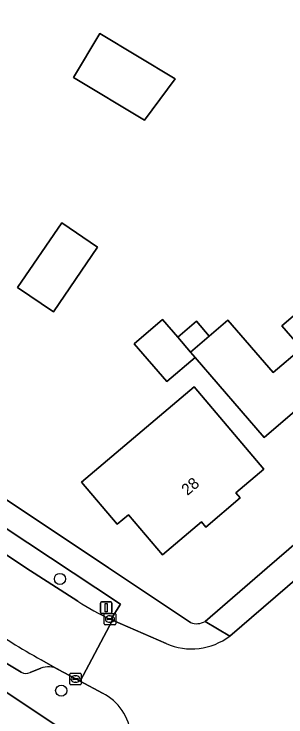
# Model space of a CAD drawing. Extents: x 161772 to 163126, y 383092 to 383917.
# Drawn here: x 162409.9 to 162433.7, y 383487 to 383548.4 of the extents above; entities that cross this region are included whole.
import ezdxf

# ---------------------------------------------------------------- set-up
doc = ezdxf.new("R2010")
doc.units = 0
for name, color, linetype in [('IMGEO_Boom', 7, 'Continuous'), ('IMGEO_Erf', 7, 'Continuous'), ('IMGEO_Groenvoorziening', 7, 'Continuous'), ('IMGEO_Kolk', 7, 'Continuous'), ('IMGEO_Lichtmast', 7, 'Continuous'), ('IMGEO_Pand', 7, 'Continuous'), ('IMGEO_Pand_nummerreeks', 7, 'Continuous'), ('IMGEO_Parkeervlak_open', 7, 'Continuous'), ('IMGEO_Rijbaan_lokaal_gesloten', 7, 'Continuous'), ('IMGEO_Rijbaan_lokaal_open', 7, 'Continuous'), ('IMGEO_Voetpad_open', 7, 'Continuous')]:
    doc.layers.add(name, color=color, linetype=linetype)

msp = doc.modelspace()

# ---------------------------------------------------------------- linework, layer by layer
at = {"layer": 'IMGEO_Boom'}
for centre in [(162413.947, 383499.021), (162414.061, 383489.255)]:
    msp.add_circle(centre, 0.489, dxfattribs=at)
at = {"layer": 'IMGEO_Erf'}
for points in [[(162462.704, 383536.779), (162483.744, 383554.98), (162500, 383574.599), (162526.947, 383607.122), (162543.804, 383623.317), (162548.918, 383628.126), (162539.791, 383641.093), (162527.133, 383641.683), (162527.105, 383641.456), (162500, 383642.583), (162442.25, 383644.984), (162375.184, 383528.714), (162418.191, 383500), (162425.357, 383495.215)], [(162426.613, 383495.312), (162432.045, 383500), (162467.807, 383530.859), (162462.704, 383536.779)], [(162434.864, 383514.039), (162431.773, 383511.379), (162425.74, 383518.391), (162423.277, 383516.272), (162420.44, 383519.57), (162422.904, 383521.69), (162424.234, 383520.144), (162425.864, 383521.546), (162426.986, 383520.242), (162428.616, 383521.645), (162432.564, 383517.058), (162435.022, 383519.173), (162433.324, 383521.146), (162436.75, 383524.093)], [(162415.606, 383482.867), (162415.154, 383485.181), (162392.934, 383500), (162369.796, 383515.431)]]:
    msp.add_lwpolyline(points, dxfattribs=at)
for points in [[(162421.34, 383539.125), (162415.121, 383542.854), (162417.421, 383546.689), (162423.997, 383542.746)], [(162413.371, 383522.37), (162410.247, 383524.505), (162414.104, 383530.149), (162417.228, 383528.014)], [(162431.752, 383508.605), (162429.312, 383506.539), (162429.685, 383506.099), (162426.677, 383503.551), (162426.294, 383504.003), (162422.898, 383501.127), (162419.935, 383504.627), (162418.955, 383503.798), (162415.83, 383507.489), (162425.654, 383515.806)]]:
    msp.add_lwpolyline(points, close=True, dxfattribs=at)
msp.add_arc((162425.891, 383496.486), 1.378, 247.22579, 301.6065, dxfattribs=at)
at = {"layer": 'IMGEO_Groenvoorziening'}
for points in [[(162418.384, 383495.476), (162419.246, 383496.818), (162417.08, 383498.245), (162405.174, 383506.099), (162404.404, 383504.955)], [(162404.404, 383504.955), (162404.125, 383504.54), (162404.195, 383504.494), (162406.79, 383502.794), (162410.958, 383500), (162415.501, 383497.08)]]:
    msp.add_lwpolyline(points, dxfattribs=at)
msp.add_arc((162428.804, 383517.598), 24.454, 237.04199, 244.77796, dxfattribs=at)
at = {"layer": 'IMGEO_Kolk'}
for p, q in [((162417.812, 383495.085), (162417.812, 383495.937)), ((162417.887, 383496.011), (162418.739, 383496.011)), ((162418.813, 383495.937), (162418.813, 383495.085)), ((162418.071, 383495.505), (162418.071, 383495.517)), ((162418.509, 383495.468), (162418.111, 383495.468)), ((162418.114, 383495.554), (162418.512, 383495.554)), ((162418.3, 383495.791), (162418.325, 383495.791)), ((162418.555, 383495.517), (162418.555, 383495.505)), ((162418.739, 383495.011), (162417.887, 383495.011)), ((162418.323, 383495.231), (162418.298, 383495.231)), ((162414.801, 383489.847), (162414.801, 383490.699)), ((162414.876, 383490.773), (162415.728, 383490.773)), ((162415.289, 383490.553), (162415.314, 383490.553)), ((162415.802, 383490.699), (162415.802, 383489.847)), ((162415.728, 383489.773), (162414.876, 383489.773)), ((162415.06, 383490.267), (162415.06, 383490.279)), ((162415.498, 383490.23), (162415.1, 383490.23)), ((162415.103, 383490.316), (162415.501, 383490.316)), ((162415.312, 383489.993), (162415.287, 383489.993)), ((162415.544, 383490.279), (162415.544, 383490.267))]:
    msp.add_line(p, q, dxfattribs=at)
for points in [[(162417.812, 383495.085), (162417.812, 383495.937)], [(162417.887, 383496.011), (162418.739, 383496.011)], [(162418.813, 383495.937), (162418.813, 383495.085)], [(162418.739, 383495.011), (162417.887, 383495.011)], [(162414.801, 383489.847), (162414.801, 383490.699)], [(162414.876, 383490.773), (162415.728, 383490.773)], [(162415.802, 383490.699), (162415.802, 383489.847)], [(162415.728, 383489.773), (162414.876, 383489.773)]]:
    msp.add_lwpolyline(points, dxfattribs=at)
for centre, radius, start, end in [((162417.889, 383495.935), 0.0765, 91.55205, 178.44795), ((162417.889, 383495.935), 0.0765, 91.55205, 178.44795), ((162418.737, 383495.935), 0.0765, 1.55205, 88.44795), ((162418.737, 383495.935), 0.0765, 1.55205, 88.44795), ((162418.111, 383495.514), 0.0403, 85.87752, 175.75265), ((162418.108, 383495.504), 0.0366, 178.93798, 274.71019), ((162418.512, 383495.511), 0.043, 264.86636, 352.45326), ((162418.516, 383495.516), 0.0386, 1.73085, 96.63898), ((162417.889, 383495.087), 0.0765, 181.55205, 268.44795), ((162417.889, 383495.087), 0.0765, 181.55205, 268.44795), ((162418.737, 383495.087), 0.0765, 271.55205, 358.44795), ((162418.737, 383495.087), 0.0765, 271.55205, 358.44795), ((162414.878, 383490.697), 0.0765, 91.55205, 178.44795), ((162414.878, 383490.697), 0.0765, 91.55205, 178.44795), ((162415.726, 383490.697), 0.0765, 1.55205, 88.44795), ((162415.726, 383490.697), 0.0765, 1.55205, 88.44795), ((162414.878, 383489.849), 0.0765, 181.55205, 268.44795), ((162414.878, 383489.849), 0.0765, 181.55205, 268.44795), ((162415.1, 383490.276), 0.0403, 85.87752, 175.75265), ((162415.097, 383490.266), 0.0366, 178.93798, 274.71019), ((162415.501, 383490.273), 0.043, 264.86636, 352.45326), ((162415.505, 383490.278), 0.0386, 1.73085, 96.63898), ((162415.726, 383489.849), 0.0765, 271.55205, 358.44795), ((162415.726, 383489.849), 0.0765, 271.55205, 358.44795)]:
    msp.add_arc(centre, radius, start, end, dxfattribs=at)
for centre, major_axis, ratio, start_param, end_param in [((162418.299, 383495.511), (-0.387, 0.002), 0.722429, 4.712389, 7.853982), ((162418.324, 383495.511), (-0.39, 0.002), 0.717154, 1.570796, 4.712389), ((162415.288, 383490.273), (-0.387, 0.002), 0.722429, 4.712389, 7.853982), ((162415.313, 383490.273), (-0.39, 0.002), 0.717154, 1.570796, 4.712389)]:
    msp.add_ellipse(centre, major_axis=major_axis, ratio=ratio, start_param=start_param, end_param=end_param, dxfattribs=at)
at = {"layer": 'IMGEO_Lichtmast'}
for p, q in [((162417.487, 383496.11), (162417.487, 383496.91)), ((162417.487, 383496.91), (162417.487, 383496.11)), ((162417.587, 383497.01), (162418.377, 383497.01)), ((162418.377, 383497.01), (162417.587, 383497.01)), ((162418.477, 383496.91), (162418.477, 383496.11)), ((162418.477, 383496.11), (162418.477, 383496.91)), ((162418.377, 383496.01), (162417.587, 383496.01)), ((162417.587, 383496.01), (162418.377, 383496.01))]:
    msp.add_line(p, q, dxfattribs=at)
msp.add_lwpolyline([(162417.907, 383496.885), (162418.057, 383496.885), (162418.057, 383496.135), (162417.907, 383496.135), (162417.907, 383496.885)], dxfattribs=at)
for centre, start, end in [((162417.587, 383496.91), 90, 180), ((162417.587, 383496.91), 90, 180), ((162418.377, 383496.91), 0, 90), ((162418.377, 383496.91), 360, 90), ((162417.587, 383496.11), 180, 270), ((162417.587, 383496.11), 180, 270), ((162418.377, 383496.11), 270, 0), ((162418.377, 383496.11), 270, 0)]:
    msp.add_arc(centre, 0.1, start, end, dxfattribs=at)
at = {"layer": 'IMGEO_Pand'}
for points in [[(162421.34, 383539.125), (162423.997, 383542.746), (162417.421, 383546.689), (162415.121, 383542.854)], [(162413.371, 383522.37), (162417.228, 383528.014), (162414.104, 383530.149), (162410.247, 383524.505)], [(162436.844, 383524.173), (162436.75, 383524.093), (162433.324, 383521.146), (162435.022, 383519.173), (162432.564, 383517.058), (162428.616, 383521.645), (162426.986, 383520.242), (162425.356, 383518.839), (162425.74, 383518.391), (162431.773, 383511.379), (162434.864, 383514.039), (162438.909, 383509.337), (162445.06, 383514.63), (162444.707, 383515.04)], [(162424.234, 383520.144), (162422.904, 383521.69), (162420.44, 383519.57), (162423.277, 383516.272), (162425.74, 383518.391), (162425.356, 383518.839)], [(162426.986, 383520.242), (162425.864, 383521.546), (162424.234, 383520.144), (162425.356, 383518.839)], [(162422.898, 383501.127), (162426.294, 383504.003), (162426.677, 383503.551), (162429.685, 383506.099), (162429.312, 383506.539), (162431.752, 383508.605), (162425.654, 383515.806), (162415.83, 383507.489), (162418.955, 383503.798), (162419.935, 383504.627)]]:
    msp.add_lwpolyline(points, close=True, dxfattribs=at)
at = {"layer": 'IMGEO_Parkeervlak_open'}
for points in [[(162398.456, 383498.732), (162407.701, 383492.642), (162409.387, 383491.566), (162410.568, 383490.866)], [(162413.794, 383491.119), (162412.302, 383491.957)], [(162411.333, 383490.832), (162412.273, 383491.21)]]:
    msp.add_lwpolyline(points, dxfattribs=at)
for centre, radius, start, end in [((162441.367, 383544.326), 59.894, 235.26876, 240.96925), ((162412.933, 383489.489), 1.844, 62.16839, 110.98386), ((162410.989, 383491.712), 0.945, 243.5433, 291.36709)]:
    msp.add_arc(centre, radius, start, end, dxfattribs=at)
at = {"layer": 'IMGEO_Rijbaan_lokaal_gesloten'}
for points in [[(162415.501, 383497.08), (162410.958, 383500), (162406.79, 383502.794), (162404.195, 383504.494), (162404.125, 383504.54), (162396.76, 383509.409)], [(162412.302, 383491.957), (162413.794, 383491.119), (162415.716, 383490.087), (162418.538, 383495.404), (162418.384, 383495.476)]]:
    msp.add_lwpolyline(points, dxfattribs=at)
for centre, radius, start, end in [((162428.804, 383517.598), 24.454, 237.04199, 244.77796), ((162441.367, 383544.326), 59.894, 235.26876, 240.96925)]:
    msp.add_arc(centre, radius, start, end, dxfattribs=at)
at = {"layer": 'IMGEO_Rijbaan_lokaal_open'}
for points in [[(162439.551, 383494.84), (162441.094, 383496.401), (162438.019, 383500), (162437.045, 383501.14), (162435.72, 383500), (162428.778, 383494.029)], [(162423.223, 383493.366), (162418.538, 383495.404), (162415.716, 383490.087), (162417.654, 383489.046)]]:
    msp.add_lwpolyline(points, dxfattribs=at)
for centre, radius, start, end in [((162425.433, 383498.455), 5.548, 246.52733, 307.085), ((162415.493, 383484.886), 4.688, 309.08784, 62.55298)]:
    msp.add_arc(centre, radius, start, end, dxfattribs=at)
at = {"layer": 'IMGEO_Voetpad_open'}
for points in [[(162549.66, 383629.858), (162548.918, 383628.126), (162543.804, 383623.317), (162526.947, 383607.122), (162500, 383574.599), (162483.744, 383554.98), (162462.704, 383536.779), (162467.807, 383530.859), (162432.045, 383500), (162426.613, 383495.312), (162428.778, 383494.029), (162435.72, 383500), (162437.045, 383501.14), (162437.192, 383501.282), (162438.691, 383502.574), (162438.438, 383502.865), (162441.394, 383505.425), (162441.654, 383505.126), (162443.112, 383506.379), (162469.395, 383528.971)], [(162418.191, 383500), (162375.184, 383528.714), (162370.031, 383531.42), (162369.74, 383530.907)], [(162371.119, 383526.076), (162373.747, 383524.572), (162373.834, 383524.516), (162374.942, 383526.139), (162387.516, 383517.815), (162386.721, 383516.648), (162389.694, 383514.682), (162390.42, 383515.798), (162396.699, 383511.708), (162397.802, 383510.956), (162397.037, 383509.82), (162404.404, 383504.955), (162405.174, 383506.099), (162417.08, 383498.245), (162419.246, 383496.818), (162418.384, 383495.476), (162418.538, 383495.404), (162423.223, 383493.366)], [(162369.796, 383515.431), (162392.934, 383500), (162415.154, 383485.181), (162415.606, 383482.867), (162418.449, 383481.247)], [(162425.357, 383495.215), (162418.191, 383500)], [(162410.568, 383490.866), (162409.387, 383491.566), (162407.701, 383492.642), (162398.456, 383498.732)], [(162428.778, 383494.029), (162426.613, 383495.312)], [(162412.273, 383491.21), (162411.333, 383490.832)], [(162417.654, 383489.046), (162415.716, 383490.087), (162413.794, 383491.119)]]:
    msp.add_lwpolyline(points, dxfattribs=at)
for centre, radius, start, end in [((162425.891, 383496.486), 1.378, 247.22579, 301.6065), ((162425.433, 383498.455), 5.548, 246.52733, 307.085), ((162412.933, 383489.489), 1.844, 62.16839, 110.98386), ((162410.989, 383491.712), 0.945, 243.5433, 291.36709), ((162415.493, 383484.886), 4.688, 309.08784, 62.55298)]:
    msp.add_arc(centre, radius, start, end, dxfattribs=at)

# ---------------------------------------------------------------- texts
at = {"layer": 'IMGEO_Pand_nummerreeks'}
msp.add_text('28', height=1, rotation=40.1841, dxfattribs=at).set_placement((162425.072, 383506.262))

doc.saveas('drawing.dxf')
